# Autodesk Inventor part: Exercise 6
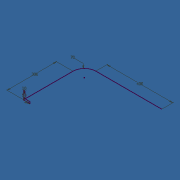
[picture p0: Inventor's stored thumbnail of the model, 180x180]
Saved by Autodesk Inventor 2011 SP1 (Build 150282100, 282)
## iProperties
Created: 2011-02
Part Number: Exercise 6
Document SubType Name: Modeling
Designer: SERGIO
Density: 1 g/cm^3
Author: SERGIO
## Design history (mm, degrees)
sketch "Sketch1"
  geometry: L1 (0, 0)-(-40, 0); L2 (0, 0)-(0, 50); L3 (0, 50)-(-10, 50); L4 (-10, 50)-(-10, 10); L5 (-10, 10)-(-40, 10); L6 (-40, 10)-(-40, 0)
  constraints: 12 end point, 5 perpendicular, 1 horizontal, 1 parallel
  dimensions: "d0" = 40 distance of L1.start L1.end; "d1" = 50 distance of L1.start L2.end; "d2" = 10 distance of L2.end L3.end
sketch "Sketch2"
  geometry: L1 (0, 0)-(0, 300); L2 (70, 370)-(470, 370); A1 r 70 centre (70, 300) between (70, 370) and (0, 300)
  constraints: 4 end point, 2 point on circle, 2 tangent, 1 centre point, 1 perpendicular, 1 vertical
  dimensions: "d3" = 300 distance of L1.start L1.end; "d4" = 400 distance of L2.start L2.end; "d5" = 70 radius of A1
